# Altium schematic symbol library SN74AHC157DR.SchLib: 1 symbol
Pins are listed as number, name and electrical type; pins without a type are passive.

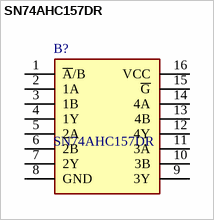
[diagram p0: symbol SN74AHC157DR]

## SN74AHC157DR
designator B?
Quadruple 2-Line To 1-Line Data Selectors / Multiplexers; Manufacturer_Name: Texas Instruments; Geometry.Height: 1.75mm
footprint SOIC127P600X175-16N
pins: 1 ~{A}/B, 2 1A, 3 1B, 4 1Y, 5 2A, 6 2B, 7 2Y, 8 GND, 9 3Y, 10 3B, 11 3A, 12 4Y, 13 4B, 14 4A, 15 ~{G}, 16 VCC (power)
